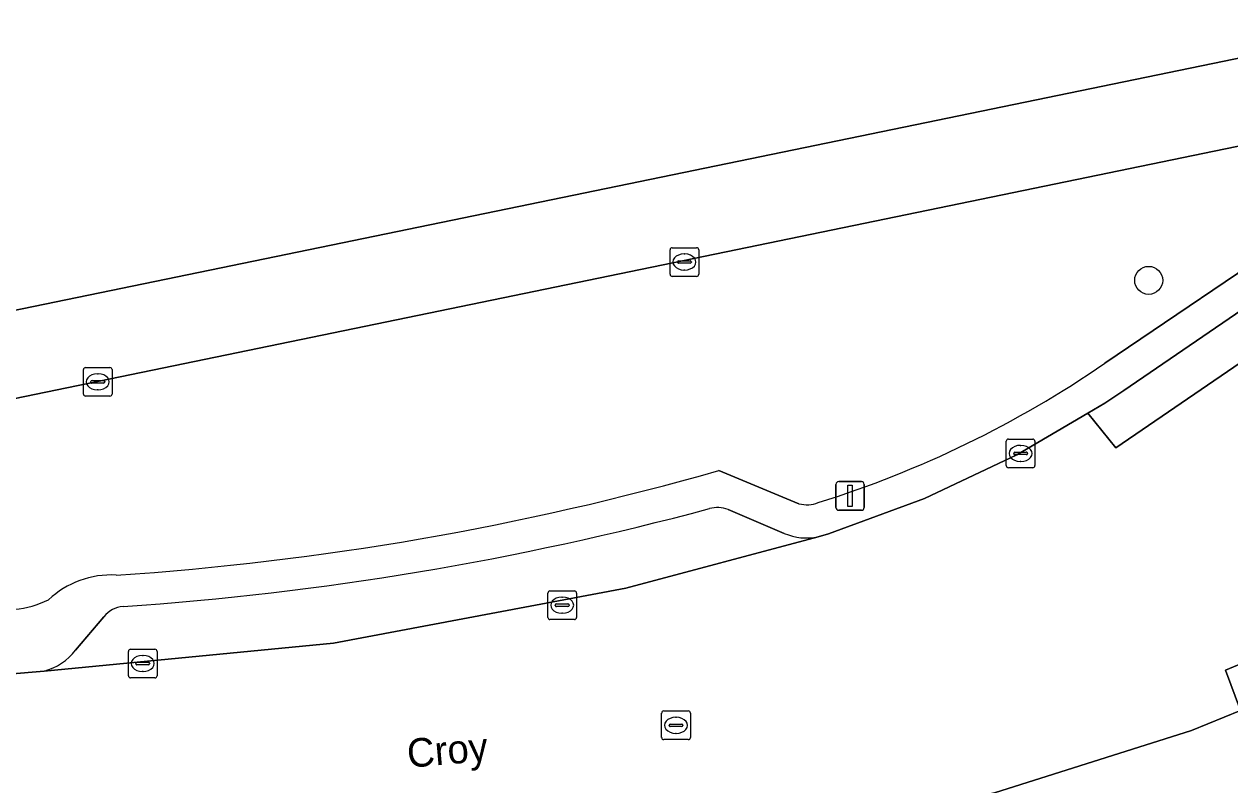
# Model space of a CAD drawing. Extents: x 157793 to 159380, y 380877 to 382313.
# Drawn here: x 158172.77 to 158214.85, y 381080.19 to 381106.74 of the extents above; entities that cross this region are included whole.
import ezdxf

# ---------------------------------------------------------------- set-up
doc = ezdxf.new("R2010")
doc.units = 0
for name, color, linetype in [('IMGEO_Boom', 7, 'Continuous'), ('IMGEO_Erf', 7, 'Continuous'), ('IMGEO_Fietspad_gesloten', 7, 'Continuous'), ('IMGEO_Groenvoorziening', 7, 'Continuous'), ('IMGEO_Kolk', 7, 'Continuous'), ('IMGEO_Lichtmast', 7, 'Continuous'), ('IMGEO_Openbare_ruimte_label', 7, 'Continuous'), ('IMGEO_Parkeervlak_open', 7, 'Continuous'), ('IMGEO_Rijbaan_lokaal_gesloten', 7, 'Continuous'), ('IMGEO_Rioolput', 7, 'Continuous'), ('IMGEO_Voetpad_open', 7, 'Continuous')]:
    doc.layers.add(name, color=color, linetype=linetype)

msp = doc.modelspace()

# ---------------------------------------------------------------- linework, layer by layer
at = {"layer": 'IMGEO_Boom'}
msp.add_circle((158212.02, 381097.8), 0.489, dxfattribs=at)
at = {"layer": 'IMGEO_Erf'}
msp.add_lwpolyline([(158164.365, 381113.429), (158165.134, 381103.303), (158168.197, 381103.575), (158168.549, 381099.472), (158168.846, 381096.013), (158217.702, 381106.076)], dxfattribs=at)
at = {"layer": 'IMGEO_Fietspad_gesloten'}
for points in [[(158221.508, 381101.89), (158220.632, 381100.732), (158220.416, 381100.508), (158220.068, 381100.171), (158219.136, 381099.419), (158217.803, 381098.506), (158211.156, 381093.954), (158210.495, 381093.516), (158209.897, 381093.165), (158210.875, 381091.959), (158220.031, 381098.214), (158221.07, 381099.052), (158222.639, 381100.584), (158223.117, 381098.1), (158223.569, 381096.666), (158224.143, 381095.28)], [(158224.262, 381095.112), (158224.428, 381094.818), (158225.376, 381093.465), (158226.428, 381092.191), (158227.578, 381091.005), (158228.689, 381090.015), (158214.705, 381084.193), (158215.221, 381082.786), (158218.935, 381084.302), (158228.371, 381088.324), (158228.543, 381088.382), (158228.732, 381088.446)]]:
    msp.add_lwpolyline(points, dxfattribs=at)
at = {"layer": 'IMGEO_Groenvoorziening'}
for points in [[(158210.493, 381094.904), (158217.198, 381099.444), (158215.438, 381102.536), (158168.317, 381092.823)], [(158197.017, 381091.16), (158199.811, 381090.005)]]:
    msp.add_lwpolyline(points, dxfattribs=at)
for centre, radius, start, end in [((158189.313, 381125.785), 37.446, 287.363, 304.4447), ((158169.319, 381188.414), 101.121, 273.77475, 285.8971), ((158200.091, 381091.02), 1.053, 254.5903, 292.1724), ((158175.791, 381084.364), 3.153, 86.6352, 133.4872), ((158172.125, 381089.705), 3.4, 254.5609, 296.099)]:
    msp.add_arc(centre, radius, start, end, dxfattribs=at)
at = {"layer": 'IMGEO_Kolk'}
for p, q in [((158195.313, 381098.014), (158195.313, 381098.866)), ((158195.388, 381098.94), (158196.24, 381098.94)), ((158195.801, 381098.72), (158195.826, 381098.72)), ((158196.314, 381098.866), (158196.314, 381098.014)), ((158195.572, 381098.434), (158195.572, 381098.446)), ((158196.01, 381098.397), (158195.612, 381098.397)), ((158195.615, 381098.483), (158196.013, 381098.483)), ((158195.824, 381098.16), (158195.799, 381098.16)), ((158196.056, 381098.446), (158196.056, 381098.434)), ((158196.24, 381097.94), (158195.388, 381097.94)), ((158174.91, 381094.758), (158175.762, 381094.758)), ((158174.835, 381093.832), (158174.835, 381094.684)), ((158175.323, 381094.538), (158175.348, 381094.538)), ((158175.836, 381094.684), (158175.836, 381093.832)), ((158175.094, 381094.252), (158175.094, 381094.264)), ((158175.532, 381094.215), (158175.134, 381094.215)), ((158175.137, 381094.301), (158175.535, 381094.301)), ((158175.346, 381093.978), (158175.321, 381093.978)), ((158175.578, 381094.264), (158175.578, 381094.252)), ((158175.762, 381093.758), (158174.91, 381093.758)), ((158207.124, 381092.26), (158207.976, 381092.26)), ((158207.049, 381091.334), (158207.049, 381092.186)), ((158207.351, 381091.803), (158207.749, 381091.803)), ((158207.537, 381092.04), (158207.562, 381092.04)), ((158208.05, 381092.186), (158208.05, 381091.334)), ((158207.308, 381091.754), (158207.308, 381091.766)), ((158207.746, 381091.717), (158207.348, 381091.717)), ((158207.56, 381091.48), (158207.535, 381091.48)), ((158207.792, 381091.766), (158207.792, 381091.754)), ((158207.976, 381091.26), (158207.124, 381091.26)), ((158191.047, 381086.036), (158191.047, 381086.888)), ((158191.122, 381086.962), (158191.974, 381086.962)), ((158192.048, 381086.888), (158192.048, 381086.036)), ((158191.306, 381086.456), (158191.306, 381086.468)), ((158191.744, 381086.419), (158191.346, 381086.419)), ((158191.349, 381086.505), (158191.747, 381086.505)), ((158191.535, 381086.742), (158191.56, 381086.742)), ((158191.79, 381086.468), (158191.79, 381086.456)), ((158191.974, 381085.962), (158191.122, 381085.962)), ((158191.558, 381086.182), (158191.533, 381086.182)), ((158176.405, 381084), (158176.405, 381084.852)), ((158176.48, 381084.926), (158177.332, 381084.926)), ((158176.893, 381084.706), (158176.918, 381084.706)), ((158177.406, 381084.852), (158177.406, 381084)), ((158176.664, 381084.42), (158176.664, 381084.432)), ((158177.102, 381084.383), (158176.704, 381084.383)), ((158176.707, 381084.469), (158177.105, 381084.469)), ((158177.148, 381084.432), (158177.148, 381084.42)), ((158177.332, 381083.926), (158176.48, 381083.926)), ((158176.916, 381084.146), (158176.891, 381084.146))]:
    msp.add_line(p, q, dxfattribs=at)
for points in [[(158195.313, 381098.014), (158195.313, 381098.866)], [(158195.388, 381098.94), (158196.24, 381098.94)], [(158196.314, 381098.866), (158196.314, 381098.014)], [(158196.24, 381097.94), (158195.388, 381097.94)], [(158174.91, 381094.758), (158175.762, 381094.758)], [(158174.835, 381093.832), (158174.835, 381094.684)], [(158175.836, 381094.684), (158175.836, 381093.832)], [(158175.762, 381093.758), (158174.91, 381093.758)], [(158207.124, 381092.26), (158207.976, 381092.26)], [(158207.049, 381091.334), (158207.049, 381092.186)], [(158208.05, 381092.186), (158208.05, 381091.334)], [(158207.976, 381091.26), (158207.124, 381091.26)], [(158191.047, 381086.036), (158191.047, 381086.888)], [(158191.122, 381086.962), (158191.974, 381086.962)], [(158192.048, 381086.888), (158192.048, 381086.036)], [(158191.974, 381085.962), (158191.122, 381085.962)], [(158176.405, 381084), (158176.405, 381084.852)], [(158176.48, 381084.926), (158177.332, 381084.926)], [(158177.406, 381084.852), (158177.406, 381084)], [(158177.332, 381083.926), (158176.48, 381083.926)]]:
    msp.add_lwpolyline(points, dxfattribs=at)
for centre, radius, start, end in [((158195.39, 381098.864), 0.0765, 91.552, 178.448), ((158195.39, 381098.864), 0.0765, 91.552, 178.448), ((158196.238, 381098.864), 0.0765, 1.552, 88.448), ((158196.238, 381098.864), 0.0765, 1.552, 88.448), ((158195.612, 381098.443), 0.0403, 85.8775, 175.7526), ((158195.609, 381098.433), 0.0366, 178.938, 274.7102), ((158196.013, 381098.44), 0.043, 264.8664, 352.4533), ((158196.017, 381098.445), 0.0386, 1.7309, 96.639), ((158195.39, 381098.016), 0.0765, 181.552, 268.448), ((158195.39, 381098.016), 0.0765, 181.552, 268.448), ((158196.238, 381098.016), 0.0765, 271.552, 358.448), ((158196.238, 381098.016), 0.0765, 271.552, 358.448), ((158174.912, 381094.682), 0.0765, 91.552, 178.448), ((158174.912, 381094.682), 0.0765, 91.552, 178.448), ((158175.76, 381094.682), 0.0765, 1.552, 88.448), ((158175.76, 381094.682), 0.0765, 1.552, 88.448), ((158175.134, 381094.261), 0.0403, 85.8775, 175.7526), ((158175.131, 381094.251), 0.0366, 178.938, 274.7102), ((158175.535, 381094.258), 0.043, 264.8664, 352.4533), ((158175.539, 381094.263), 0.0386, 1.7309, 96.639), ((158174.912, 381093.834), 0.0765, 181.552, 268.448), ((158174.912, 381093.834), 0.0765, 181.552, 268.448), ((158175.76, 381093.834), 0.0765, 271.552, 358.448), ((158175.76, 381093.834), 0.0765, 271.552, 358.448), ((158207.126, 381092.184), 0.0765, 91.552, 178.448), ((158207.126, 381092.184), 0.0765, 91.552, 178.448), ((158207.974, 381092.184), 0.0765, 1.552, 88.448), ((158207.974, 381092.184), 0.0765, 1.552, 88.448), ((158207.348, 381091.763), 0.0403, 85.8775, 175.7526), ((158207.753, 381091.765), 0.0386, 1.7309, 96.639), ((158207.345, 381091.753), 0.0366, 178.938, 274.7102), ((158207.749, 381091.76), 0.043, 264.8664, 352.4533), ((158207.126, 381091.336), 0.0765, 181.552, 268.448), ((158207.126, 381091.336), 0.0765, 181.552, 268.448), ((158207.974, 381091.336), 0.0765, 271.552, 358.448), ((158207.974, 381091.336), 0.0765, 271.552, 358.448), ((158191.124, 381086.886), 0.0765, 91.552, 178.448), ((158191.124, 381086.886), 0.0765, 91.552, 178.448), ((158191.972, 381086.886), 0.0765, 1.552, 88.448), ((158191.972, 381086.886), 0.0765, 1.552, 88.448), ((158191.346, 381086.465), 0.0403, 85.8775, 175.7526), ((158191.343, 381086.455), 0.0366, 178.938, 274.7102), ((158191.747, 381086.462), 0.043, 264.8664, 352.4533), ((158191.751, 381086.467), 0.0386, 1.7309, 96.639), ((158191.124, 381086.038), 0.0765, 181.552, 268.448), ((158191.124, 381086.038), 0.0765, 181.552, 268.448), ((158191.972, 381086.038), 0.0765, 271.552, 358.448), ((158191.972, 381086.038), 0.0765, 271.552, 358.448), ((158176.482, 381084.85), 0.0765, 91.552, 178.448), ((158176.482, 381084.85), 0.0765, 91.552, 178.448), ((158177.33, 381084.85), 0.0765, 1.552, 88.448), ((158177.33, 381084.85), 0.0765, 1.552, 88.448), ((158176.704, 381084.429), 0.0403, 85.8775, 175.7526), ((158176.701, 381084.419), 0.0366, 178.938, 274.7102), ((158177.105, 381084.426), 0.043, 264.8664, 352.4533), ((158177.109, 381084.431), 0.0386, 1.7309, 96.639), ((158176.482, 381084.002), 0.0765, 181.552, 268.448), ((158176.482, 381084.002), 0.0765, 181.552, 268.448), ((158177.33, 381084.002), 0.0765, 271.552, 358.448), ((158177.33, 381084.002), 0.0765, 271.552, 358.448)]:
    msp.add_arc(centre, radius, start, end, dxfattribs=at)
for centre, major_axis, ratio, start_param, end_param in [((158195.8, 381098.44), (-0.387, 0.002), 0.722429, 4.712389, 7.853982), ((158195.825, 381098.44), (-0.39, 0.002), 0.717154, 1.570796, 4.712389), ((158175.322, 381094.258), (-0.387, 0.002), 0.722429, 4.712389, 7.853982), ((158175.347, 381094.258), (-0.39, 0.002), 0.717154, 1.570796, 4.712389), ((158207.536, 381091.76), (-0.387, 0.002), 0.722429, 4.712389, 7.853982), ((158207.561, 381091.76), (-0.39, 0.002), 0.717154, 1.570796, 4.712389), ((158191.534, 381086.462), (-0.387, 0.002), 0.722429, 4.712389, 7.853982), ((158191.559, 381086.462), (-0.39, 0.002), 0.717154, 1.570796, 4.712389), ((158176.892, 381084.426), (-0.387, 0.002), 0.722429, 4.712389, 7.853982), ((158176.917, 381084.426), (-0.39, 0.002), 0.717154, 1.570796, 4.712389)]:
    msp.add_ellipse(centre, major_axis=major_axis, ratio=ratio, start_param=start_param, end_param=end_param, dxfattribs=at)
at = {"layer": 'IMGEO_Lichtmast'}
for p, q in [((158201.1, 381089.877), (158201.1, 381090.677)), ((158201.1, 381090.677), (158201.1, 381089.877)), ((158201.2, 381090.777), (158201.99, 381090.777)), ((158201.99, 381090.777), (158201.2, 381090.777)), ((158202.09, 381090.677), (158202.09, 381089.877)), ((158202.09, 381089.877), (158202.09, 381090.677)), ((158201.99, 381089.777), (158201.2, 381089.777)), ((158201.2, 381089.777), (158201.99, 381089.777))]:
    msp.add_line(p, q, dxfattribs=at)
msp.add_lwpolyline([(158201.52, 381090.652), (158201.67, 381090.652), (158201.67, 381089.902), (158201.52, 381089.902), (158201.52, 381090.652)], dxfattribs=at)
for centre, start, end in [((158201.2, 381090.677), 90, 180), ((158201.2, 381090.677), 90, 180), ((158201.99, 381090.677), 0, 90), ((158201.99, 381090.677), 360, 90), ((158201.2, 381089.877), 180, 270), ((158201.2, 381089.877), 180, 270), ((158201.99, 381089.877), 270, 0), ((158201.99, 381089.877), 270, 0)]:
    msp.add_arc(centre, 0.1, start, end, dxfattribs=at)
at = {"layer": 'IMGEO_Parkeervlak_open'}
for points in [[(158199.3, 381088.967), (158197.338, 381089.801)], [(158193.766, 381087.058), (158200.484, 381088.849)], [(158173.465, 381084.163), (158183.564, 381085.139), (158193.766, 381087.058)], [(158175.547, 381086.058), (158174.563, 381084.896)]]:
    msp.add_lwpolyline(points, dxfattribs=at)
for centre, radius, start, end in [((158168.855, 381193.417), 107.257, 273.93813, 285.03827), ((158196.962, 381088.815), 1.055, 69.1199, 105.2776), ((158200.084, 381090.832), 2.023, 247.2068, 281.4104), ((158176.283, 381085.479), 0.936, 93.7732, 141.7789), ((158172.963, 381086.104), 2.004, 284.4993, 322.953)]:
    msp.add_arc(centre, radius, start, end, dxfattribs=at)
at = {"layer": 'IMGEO_Rijbaan_lokaal_gesloten'}
for points in [[(158220.031, 381098.214), (158210.875, 381091.959), (158209.897, 381093.165), (158207.419, 381091.71), (158204.195, 381090.187), (158200.847, 381088.958), (158200.484, 381088.849), (158193.766, 381087.058), (158183.564, 381085.139), (158173.465, 381084.163), (158172.225, 381084.05)], [(158167.649, 381075.632), (158184.529, 381077.082), (158199.599, 381078.363), (158206.642, 381079.916), (158213.519, 381082.092), (158215.221, 381082.786), (158214.705, 381084.193), (158228.689, 381090.015)]]:
    msp.add_lwpolyline(points, dxfattribs=at)
at = {"layer": 'IMGEO_Rioolput'}
for p, q in [((158195.02, 381081.844), (158195.02, 381082.696)), ((158195.095, 381082.77), (158195.947, 381082.77)), ((158195.508, 381082.55), (158195.533, 381082.55)), ((158196.021, 381082.696), (158196.021, 381081.844)), ((158195.279, 381082.264), (158195.279, 381082.276)), ((158195.717, 381082.227), (158195.319, 381082.227)), ((158195.322, 381082.313), (158195.72, 381082.313)), ((158195.763, 381082.276), (158195.763, 381082.264)), ((158195.947, 381081.77), (158195.095, 381081.77)), ((158195.531, 381081.99), (158195.506, 381081.99))]:
    msp.add_line(p, q, dxfattribs=at)
for points in [[(158195.02, 381081.844), (158195.02, 381082.696)], [(158195.095, 381082.77), (158195.947, 381082.77)], [(158196.021, 381082.696), (158196.021, 381081.844)], [(158195.947, 381081.77), (158195.095, 381081.77)]]:
    msp.add_lwpolyline(points, dxfattribs=at)
for centre, radius, start, end in [((158195.097, 381082.694), 0.0765, 91.552, 178.448), ((158195.097, 381082.694), 0.0765, 91.552, 178.448), ((158195.945, 381082.694), 0.0765, 1.552, 88.448), ((158195.945, 381082.694), 0.0765, 1.552, 88.448), ((158195.319, 381082.273), 0.0403, 85.8775, 175.7526), ((158195.316, 381082.263), 0.0366, 178.938, 274.7102), ((158195.72, 381082.27), 0.043, 264.8664, 352.4533), ((158195.724, 381082.275), 0.0386, 1.7309, 96.639), ((158195.097, 381081.846), 0.0765, 181.552, 268.448), ((158195.097, 381081.846), 0.0765, 181.552, 268.448), ((158195.945, 381081.846), 0.0765, 271.552, 358.448), ((158195.945, 381081.846), 0.0765, 271.552, 358.448)]:
    msp.add_arc(centre, radius, start, end, dxfattribs=at)
for centre, major_axis, ratio, start_param, end_param in [((158195.507, 381082.27), (-0.387, 0.002), 0.722429, 4.712389, 7.853982), ((158195.532, 381082.27), (-0.39, 0.002), 0.717154, 1.570796, 4.712389)]:
    msp.add_ellipse(centre, major_axis=major_axis, ratio=ratio, start_param=start_param, end_param=end_param, dxfattribs=at)
at = {"layer": 'IMGEO_Voetpad_open'}
for points in [[(158215.438, 381102.536), (158217.702, 381106.076), (158168.846, 381096.013), (158168.549, 381099.472), (158165.486, 381099.2), (158166.373, 381090.041)], [(158168.317, 381092.823), (158215.438, 381102.536)], [(158200.484, 381088.849), (158200.847, 381088.958), (158204.195, 381090.187), (158207.419, 381091.71), (158209.897, 381093.165), (158210.495, 381093.516), (158211.156, 381093.954), (158217.803, 381098.506), (158217.198, 381099.444), (158210.493, 381094.904)], [(158199.811, 381090.005), (158197.017, 381091.16)], [(158166.743, 381089.047), (158166.588, 381089.334), (158166.411, 381089.724), (158166.985, 381085.48), (158167.948, 381085.014), (158168.948, 381084.636), (158169.979, 381084.349), (158171.03, 381084.155), (158172.095, 381084.056), (158172.225, 381084.05), (158173.465, 381084.163)], [(158197.338, 381089.801), (158199.3, 381088.967)], [(158174.563, 381084.896), (158175.547, 381086.058)], [(158220.593, 381079.208), (158221.055, 381079.401), (158218.935, 381084.302), (158215.221, 381082.786), (158213.519, 381082.092), (158206.642, 381079.916), (158199.599, 381078.363), (158184.529, 381077.082), (158184.733, 381074.138), (158184.748, 381074.01), (158190.893, 381074.499), (158197.853, 381075.053)]]:
    msp.add_lwpolyline(points, dxfattribs=at)
for centre, radius, start, end in [((158189.313, 381125.785), 37.446, 287.363, 304.4447), ((158169.319, 381188.414), 101.121, 273.77475, 285.8971), ((158168.855, 381193.417), 107.257, 273.93813, 285.03827), ((158196.962, 381088.815), 1.055, 69.1199, 105.2776), ((158200.091, 381091.02), 1.053, 254.5903, 292.1724), ((158200.084, 381090.832), 2.023, 247.2068, 281.4104), ((158175.791, 381084.364), 3.153, 86.6352, 133.4872), ((158172.125, 381089.705), 3.4, 254.5609, 296.099), ((158176.283, 381085.479), 0.936, 93.7732, 141.7789), ((158172.963, 381086.104), 2.004, 284.4993, 322.953)]:
    msp.add_arc(centre, radius, start, end, dxfattribs=at)

# ---------------------------------------------------------------- texts
at = {"layer": 'IMGEO_Openbare_ruimte_label'}
msp.add_text('Croy', height=1, rotation=5.0492, dxfattribs=at).set_placement((158186.176, 381080.785))

doc.saveas('drawing.dxf')
